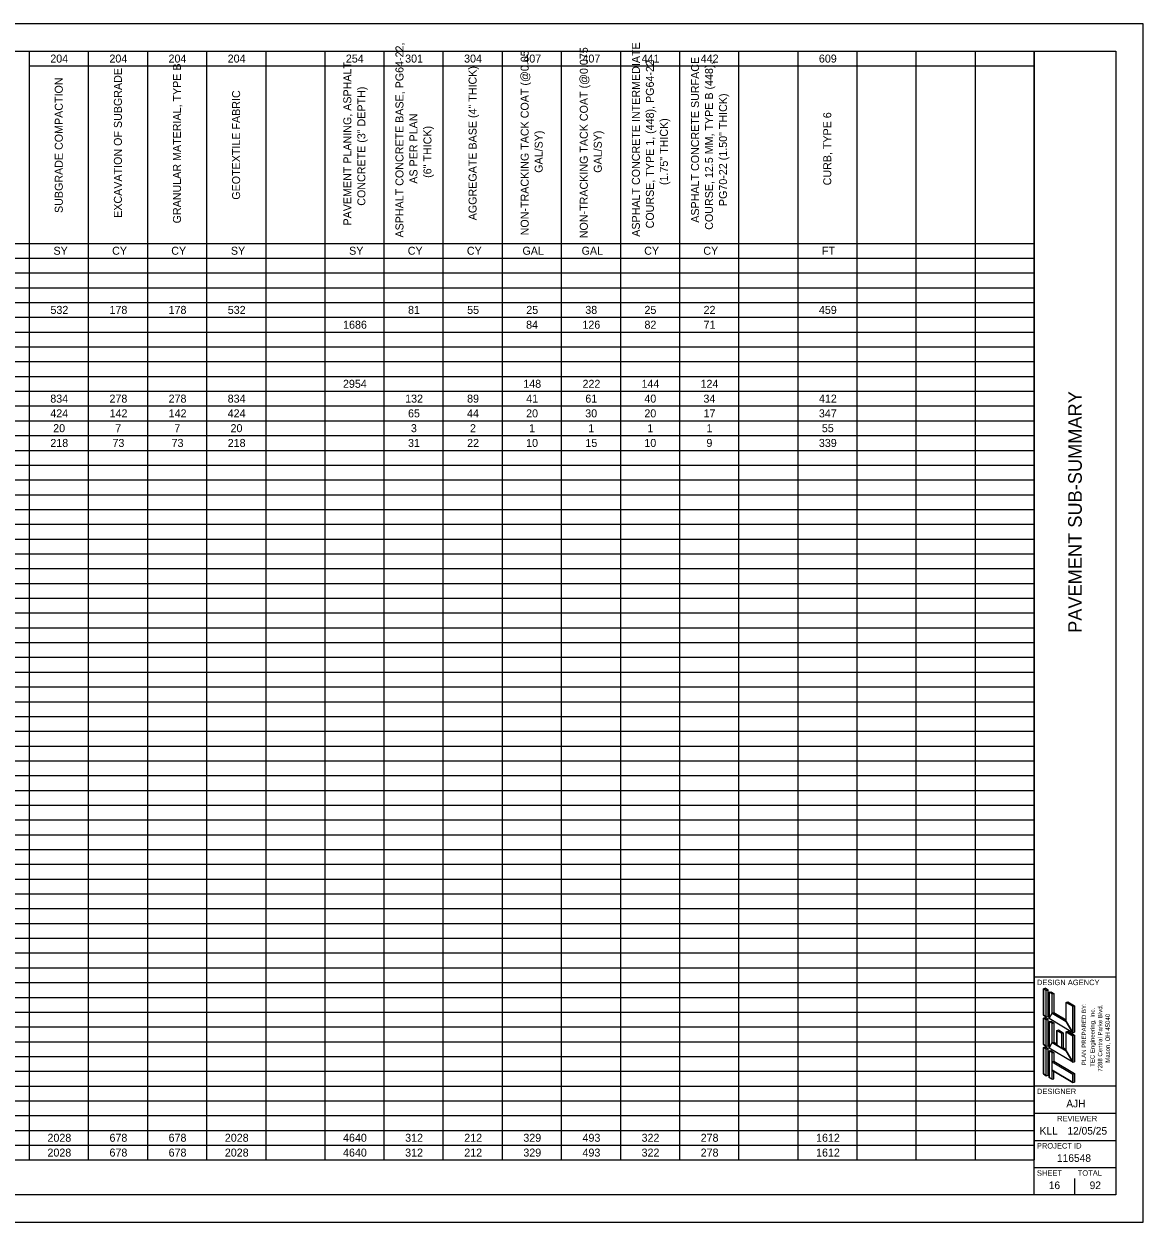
# Model space of a CAD drawing. Extents: x 0 to 34, y 0 to 22.
# Drawn here: x 13.44 to 34, y 0 to 22 of the extents above; entities that cross this region are included whole.
import ezdxf

# ---------------------------------------------------------------- set-up
doc = ezdxf.new("R2010")
doc.units = 0
for name, color, linetype in [('Default', 7, 'Continuous'), ('SH_Border', 7, 'Continuous'), ('SH_Cut_Line', 7, 'Continuous'), ('SH_Data', 7, 'Continuous'), ('SH_Text', 7, 'Continuous')]:
    doc.layers.add(name, color=color, linetype=linetype)

msp = doc.modelspace()

# ---------------------------------------------------------------- linework, layer by layer
at = {"layer": 'SH_Border'}
for p, q in [((32, 0.5), (32, 21.5)), ((32, 4.5), (33.5, 4.5)), ((32, 2.5), (33.5, 2.5)), ((32, 2), (33.5, 2)), ((32, 1.5), (33.5, 1.5)), ((32, 1), (33.5, 1))]:
    msp.add_line(p, q, dxfattribs=at)
msp.add_lwpolyline([(1.5, 21.5), (33.5, 21.5), (33.5, 0.5), (1.5, 0.5)], close=True, dxfattribs=at)
at = {"layer": 'SH_Cut_Line'}
msp.add_lwpolyline([(0, 0), (34, 0), (34, 22), (0, 22)], close=True, dxfattribs=at)
at = {"layer": 'SH_Data'}
for p, q in [((32.75, 3.5), (32.75, 3.5)), ((32.375, 0.675), (32.375, 0.675)), ((32.75, 0.5), (32.75, 0.8))]:
    msp.add_line(p, q, dxfattribs=at)
at = {"layer": 'SH_Text'}
for p, q in [((1.5, 21.5), (32, 21.5)), ((13.54, 21.5), (13.54, 1.14)), ((14.626, 21.5), (14.626, 1.14)), ((15.712, 21.5), (15.712, 1.14)), ((16.798, 21.5), (16.798, 1.14)), ((17.884, 21.5), (17.884, 1.14)), ((18.97, 21.5), (18.97, 1.14)), ((20.055, 21.5), (20.055, 1.14)), ((21.141, 21.5), (21.141, 1.14)), ((22.227, 21.5), (22.227, 1.14)), ((23.313, 21.5), (23.313, 1.14)), ((24.399, 21.5), (24.399, 1.14)), ((25.485, 21.5), (25.485, 1.14)), ((26.571, 21.5), (26.571, 1.14)), ((27.657, 21.5), (27.657, 1.14)), ((28.742, 21.5), (28.742, 1.14)), ((29.828, 21.5), (29.828, 1.14)), ((30.914, 21.5), (30.914, 1.14)), ((32, 21.5), (32, 1.14)), ((13.54, 21.229), (32, 21.229)), ((8.111, 17.971), (32, 17.971)), ((1.5, 17.699), (32, 17.699)), ((1.5, 17.428), (32, 17.428)), ((1.5, 17.157), (32, 17.157)), ((1.5, 16.885), (32, 16.885)), ((1.5, 16.614), (32, 16.614)), ((1.5, 16.342), (32, 16.342)), ((1.5, 16.071), (32, 16.071)), ((1.5, 15.799), (32, 15.799)), ((1.5, 15.528), (32, 15.528)), ((1.5, 15.256), (32, 15.256)), ((1.5, 14.985), (32, 14.985)), ((1.5, 14.713), (32, 14.713)), ((1.5, 14.442), (32, 14.442)), ((1.5, 14.17), (32, 14.17)), ((1.5, 13.899), (32, 13.899)), ((1.5, 13.627), (32, 13.627)), ((1.5, 13.356), (32, 13.356)), ((1.5, 13.085), (32, 13.085)), ((1.5, 12.813), (32, 12.813)), ((1.5, 12.542), (32, 12.542)), ((1.5, 12.27), (32, 12.27)), ((1.5, 11.999), (32, 11.999)), ((1.5, 11.727), (32, 11.727)), ((1.5, 11.456), (32, 11.456)), ((1.5, 11.184), (32, 11.184)), ((1.5, 10.913), (32, 10.913)), ((1.5, 10.641), (32, 10.641)), ((1.5, 10.37), (32, 10.37)), ((1.5, 10.098), (32, 10.098)), ((1.5, 9.827), (32, 9.827)), ((1.5, 9.555), (32, 9.555)), ((1.5, 9.284), (32, 9.284)), ((1.5, 9.013), (32, 9.013)), ((1.5, 8.741), (32, 8.741)), ((1.5, 8.47), (32, 8.47)), ((1.5, 8.198), (32, 8.198)), ((1.5, 7.927), (32, 7.927)), ((1.5, 7.655), (32, 7.655)), ((1.5, 7.384), (32, 7.384)), ((1.5, 7.112), (32, 7.112)), ((1.5, 6.841), (32, 6.841)), ((1.5, 6.569), (32, 6.569)), ((1.5, 6.298), (32, 6.298)), ((1.5, 6.026), (32, 6.026)), ((1.5, 5.755), (32, 5.755)), ((1.5, 5.484), (32, 5.484)), ((1.5, 5.212), (32, 5.212)), ((1.5, 4.941), (32, 4.941)), ((1.5, 4.669), (32, 4.669)), ((1.5, 4.398), (32, 4.398)), ((32.169, 4.285), (32.201, 4.294)), ((32.169, 3.799), (32.169, 4.285)), ((32.223, 4.253), (32.169, 4.285)), ((32.255, 4.261), (32.201, 4.294)), ((32.223, 4.253), (32.255, 4.261)), ((32.223, 3.767), (32.223, 4.253)), ((32.255, 3.775), (32.255, 4.261)), ((32.277, 4.221), (32.309, 4.229)), ((32.331, 4.188), (32.277, 4.221)), ((32.277, 3.735), (32.277, 4.221)), ((32.309, 4.229), (32.363, 4.196)), ((32.331, 4.188), (32.363, 4.196)), ((32.331, 3.837), (32.331, 4.188)), ((32.363, 4.196), (32.363, 3.845)), ((1.5, 4.126), (32, 4.126)), ((32.587, 4.034), (32.62, 4.042)), ((32.587, 3.683), (32.587, 4.034)), ((32.709, 3.961), (32.587, 4.034)), ((32.62, 4.042), (32.741, 3.97)), ((32.709, 3.961), (32.741, 3.97)), ((32.709, 3.475), (32.709, 3.961)), ((32.741, 3.97), (32.741, 3.484)), ((1.5, 3.855), (32, 3.855)), ((32.223, 3.767), (32.169, 3.799)), ((32.169, 3.745), (32.201, 3.754)), ((32.169, 3.259), (32.169, 3.745)), ((32.223, 3.713), (32.169, 3.745)), ((32.255, 3.722), (32.201, 3.754)), ((32.223, 3.767), (32.255, 3.775)), ((32.331, 3.837), (32.363, 3.845)), ((32.587, 3.683), (32.331, 3.837)), ((32.363, 3.845), (32.587, 3.711)), ((1.5, 3.583), (32, 3.583)), ((32.223, 3.713), (32.255, 3.722)), ((32.223, 3.227), (32.223, 3.713)), ((32.255, 3.236), (32.255, 3.722)), ((32.709, 3.475), (32.277, 3.735)), ((32.277, 3.681), (32.309, 3.689)), ((32.277, 3.195), (32.277, 3.681)), ((32.331, 3.648), (32.277, 3.681)), ((32.309, 3.689), (32.363, 3.656)), ((32.331, 3.648), (32.363, 3.656)), ((32.331, 3.297), (32.331, 3.648)), ((32.363, 3.656), (32.363, 3.305)), ((32.415, 3.519), (32.448, 3.527)), ((32.448, 3.527), (32.535, 3.474)), ((1.5, 3.312), (32, 3.312)), ((32.331, 3.297), (32.363, 3.305)), ((32.363, 3.305), (32.415, 3.274)), ((32.415, 3.519), (32.415, 3.247)), ((32.415, 3.519), (32.503, 3.466)), ((32.503, 3.466), (32.535, 3.474)), ((32.503, 3.466), (32.503, 3.194)), ((32.535, 3.474), (32.535, 3.202)), ((32.587, 3.494), (32.62, 3.502)), ((32.587, 3.143), (32.587, 3.494)), ((32.709, 3.421), (32.587, 3.494)), ((32.62, 3.502), (32.741, 3.43)), ((32.709, 3.475), (32.741, 3.484)), ((32.709, 3.421), (32.741, 3.43)), ((32.709, 2.935), (32.709, 3.421)), ((32.741, 3.43), (32.741, 2.944)), ((32.223, 3.227), (32.169, 3.259)), ((32.169, 3.205), (32.201, 3.215)), ((32.169, 2.719), (32.169, 3.205)), ((32.223, 3.173), (32.169, 3.205)), ((32.255, 3.181), (32.201, 3.215)), ((32.222, 3.173), (32.255, 3.181)), ((32.223, 3.227), (32.255, 3.236)), ((32.223, 2.687), (32.223, 3.173)), ((32.255, 2.695), (32.255, 3.181)), ((32.709, 2.935), (32.277, 3.195)), ((32.277, 3.141), (32.309, 3.151)), ((32.331, 3.108), (32.277, 3.141)), ((32.277, 2.655), (32.277, 3.141)), ((32.309, 3.151), (32.363, 3.116)), ((32.415, 3.247), (32.331, 3.297)), ((32.331, 3.108), (32.363, 3.116)), ((32.331, 2.944), (32.331, 3.108)), ((32.363, 3.116), (32.363, 2.952)), ((32.503, 3.194), (32.535, 3.202)), ((32.587, 3.143), (32.503, 3.194)), ((32.535, 3.202), (32.587, 3.171)), ((1.5, 3.04), (32, 3.04)), ((32.331, 2.944), (32.363, 2.952)), ((32.331, 2.944), (32.709, 2.717)), ((32.363, 2.952), (32.741, 2.725)), ((32.709, 2.935), (32.741, 2.944)), ((1.5, 2.769), (32, 2.769)), ((32.223, 2.687), (32.169, 2.719)), ((32.223, 2.687), (32.255, 2.695)), ((32.331, 2.622), (32.277, 2.655)), ((32.331, 2.787), (32.709, 2.56)), ((32.331, 2.622), (32.331, 2.787)), ((32.363, 2.63), (32.363, 2.767)), ((32.709, 2.717), (32.741, 2.725)), ((32.709, 2.56), (32.709, 2.717)), ((32.741, 2.725), (32.741, 2.568)), ((1.5, 2.497), (32, 2.497)), ((32.331, 2.622), (32.363, 2.63)), ((32.709, 2.56), (32.741, 2.568)), ((1.5, 2.226), (32, 2.226)), ((1.5, 1.954), (32, 1.954)), ((1.5, 1.683), (32, 1.683)), ((1.5, 1.412), (32, 1.412)), ((1.5, 1.14), (32, 1.14))]:
    msp.add_line(p, q, dxfattribs=at)
for points in [[(32.169, 3.799), (32.223, 3.767), (32.223, 4.253), (32.169, 4.285)], [(32.277, 3.735), (32.331, 3.837), (32.331, 4.188), (32.277, 4.221)], [(32.709, 3.475), (32.587, 3.683), (32.587, 4.034), (32.709, 3.961)], [(32.169, 3.259), (32.223, 3.227), (32.223, 3.713), (32.169, 3.745)], [(32.277, 3.735), (32.331, 3.837), (32.587, 3.683), (32.709, 3.475)], [(32.277, 3.195), (32.331, 3.297), (32.331, 3.648), (32.277, 3.681)], [(32.415, 3.247), (32.415, 3.519), (32.503, 3.466), (32.503, 3.194)], [(32.709, 2.935), (32.587, 3.143), (32.587, 3.494), (32.709, 3.421)], [(32.169, 2.719), (32.223, 2.687), (32.223, 3.173), (32.169, 3.205)], [(32.277, 3.195), (32.331, 3.297), (32.587, 3.143), (32.709, 2.935)], [(32.277, 2.655), (32.331, 2.622), (32.331, 3.108), (32.277, 3.141)], [(32.331, 2.787), (32.331, 2.944), (32.709, 2.717), (32.709, 2.56)]]:
    msp.add_lwpolyline(points, close=True, dxfattribs=at)

# ---------------------------------------------------------------- texts
at = {"layer": 'Default'}
for s, p in [('PLAN PREPARED BY:', (32.954, 2.88)), ('TEC Engineering, Inc.', (33.11, 2.851)), ('7288 Central Parke Blvd.', (33.25, 2.762)), ('Mason, OH 45040', (33.39, 2.925))]:
    msp.add_text(s, height=0.08, rotation=90, dxfattribs=at).set_placement(p)
at = {"layer": 'SH_Data'}
msp.add_text('PAVEMENT SUB-SUMMARY', height=0.25, rotation=90, dxfattribs=at).set_placement((32.875, 10.818))
for s, height, p in [('DESIGN AGENCY', 0.1, (32.05, 4.35)), ('DESIGNER', 0.1, (32.05, 2.35)), ('AJH', 0.14, (32.59, 2.105)), ('REVIEWER', 0.1, (32.422, 1.85)), ('KLL', 0.14, (32.101, 1.605)), ('12/05/25', 0.14, (32.611, 1.605)), ('PROJECT ID', 0.1, (32.05, 1.35)), ('116548', 0.14, (32.419, 1.105)), ('SHEET', 0.1, (32.05, 0.85)), ('TOTAL', 0.1, (32.8, 0.85)), ('16', 0.14, (32.268, 0.605)), ('92', 0.14, (33.019, 0.605))]:
    msp.add_text(s, height=height, dxfattribs=at).set_placement(p)
at = {"layer": 'SH_Text'}
for s, height, p in [('ASPHALT CONCRETE BASE, PG64-22, ', 0.14691, (20.415, 18.078)), ('NON-TRACKING TACK COAT (@0.075 ', 0.14691, (23.801, 18.065)), ('ASPHALT CONCRETE INTERMEDIATE ', 0.14691, (24.758, 18.093)), ('NON-TRACKING TACK COAT (@0.05 ', 0.14691, (22.715, 18.118)), ('ASPHALT CONCRETE SURFACE ', 0.14691, (25.844, 18.35)), ('EXCAVATION OF SUBGRADE', 0.14691, (15.243, 18.44)), ('GRANULAR MATERIAL, TYPE B', 0.14691, (16.328, 18.338)), ('PAVEMENT PLANING, ASPHALT ', 0.14691, (19.457, 18.299)), ('AGGREGATE BASE (4" THICK)', 0.14691, (21.758, 18.395)), ('COURSE, TYPE 1, (448), PG64-22 ', 0.14691, (25.015, 18.246)), ('COURSE, 12.5 MM, TYPE B (448), ', 0.14691, (26.101, 18.22)), ('SUBGRADE COMPACTION', 0.14691, (14.157, 18.529)), ('GEOTEXTILE FABRIC', 0.14691, (17.414, 18.773)), ('CONCRETE (3" DEPTH)', 0.14691, (19.715, 18.662)), ('PG70-22 (1.50" THICK)', 0.14691, (26.358, 18.656)), ('AS PER PLAN', 0.14691, (20.672, 19.067)), ('(1.75" THICK)', 0.14691, (25.272, 19.042)), ('CURB, TYPE 6', 0.14691, (28.273, 19.036)), ('(6" THICK)', 0.1469, (20.929, 19.174)), ('GAL/SY)', 0.1469, (22.972, 19.267)), ('GAL/SY)', 0.1469, (24.058, 19.267))]:
    msp.add_text(s, height=height, rotation=90, dxfattribs=at).set_placement(p)
for s, height, p in [('204', 0.1469, (13.928, 21.291)), ('204', 0.1469, (15.014, 21.291)), ('204', 0.1469, (16.1, 21.291)), ('204', 0.1469, (17.186, 21.291)), ('254', 0.1469, (19.357, 21.291)), ('301', 0.1469, (20.446, 21.291)), ('304', 0.1469, (21.529, 21.291)), ('407', 0.1469, (22.617, 21.291)), ('407', 0.1469, (23.703, 21.291)), ('441', 0.1469, (24.789, 21.291)), ('442', 0.1469, (25.875, 21.291)), ('609', 0.1469, (28.046, 21.291)), ('SY', 0.1469, (13.987, 17.762)), ('CY', 0.1469, (15.064, 17.762)), ('CY', 0.1469, (16.15, 17.762)), ('SY', 0.1469, (17.245, 17.762)), ('SY', 0.1469, (19.417, 17.762)), ('CY', 0.1469, (20.494, 17.762)), ('CY', 0.1469, (21.58, 17.762)), ('GAL', 0.1469, (22.601, 17.762)), ('GAL', 0.1469, (23.687, 17.762)), ('CY', 0.1469, (24.837, 17.762)), ('CY', 0.1469, (25.923, 17.762)), ('FT', 0.1469, (28.102, 17.762)), ('532', 0.1469, (13.931, 16.676)), ('178', 0.1469, (15.015, 16.676)), ('178', 0.1469, (16.101, 16.676)), ('532', 0.1469, (17.188, 16.676)), ('81', 0.1469, (20.499, 16.676)), ('55', 0.1469, (21.585, 16.676)), ('25', 0.1469, (22.671, 16.676)), ('38', 0.1469, (23.755, 16.676)), ('25', 0.1469, (24.842, 16.676)), ('22', 0.1469, (25.928, 16.676)), ('459', 0.1469, (28.046, 16.676)), ('1686', 0.1469, (19.306, 16.404)), ('84', 0.1469, (22.668, 16.404)), ('126', 0.1469, (23.702, 16.404)), ('82', 0.1469, (24.842, 16.404)), ('71', 0.1469, (25.928, 16.404)), ('2954', 0.1469, (19.304, 15.319)), ('148', 0.1469, (22.616, 15.319)), ('222', 0.1469, (23.704, 15.319)), ('144', 0.1469, (24.787, 15.319)), ('124', 0.1469, (25.872, 15.319)), ('834', 0.1469, (13.928, 15.047)), ('278', 0.1469, (15.015, 15.047)), ('278', 0.1469, (16.101, 15.047)), ('834', 0.1469, (17.186, 15.047)), ('132', 0.1469, (20.446, 15.047)), ('89', 0.1469, (21.584, 15.047)), ('41', 0.1469, (22.67, 15.047)), ('61', 0.1469, (23.756, 15.047)), ('40', 0.1469, (24.84, 15.047)), ('34', 0.1469, (25.925, 15.047)), ('412', 0.1469, (28.047, 15.047)), ('424', 0.1469, (13.928, 14.776)), ('142', 0.1469, (15.017, 14.776)), ('142', 0.1469, (16.102, 14.776)), ('424', 0.1469, (17.186, 14.776)), ('65', 0.1469, (20.499, 14.776)), ('44', 0.1469, (21.582, 14.776)), ('20', 0.1469, (22.668, 14.776)), ('30', 0.1469, (23.754, 14.776)), ('20', 0.1469, (24.84, 14.776)), ('17', 0.1469, (25.927, 14.776)), ('347', 0.1469, (28.046, 14.776)), ('20', 0.1469, (13.981, 14.504)), ('7', 0.147, (15.121, 14.504)), ('7', 0.147, (16.207, 14.504)), ('20', 0.1469, (17.239, 14.504)), ('3', 0.147, (20.552, 14.504)), ('2', 0.147, (21.637, 14.504)), ('1', 0.147, (22.723, 14.504)), ('1', 0.147, (23.809, 14.504)), ('1', 0.147, (24.895, 14.504)), ('1', 0.147, (25.981, 14.504)), ('55', 0.1469, (28.1, 14.504)), ('218', 0.1469, (13.929, 14.233)), ('73', 0.1469, (15.07, 14.233)), ('73', 0.1469, (16.156, 14.233)), ('218', 0.1469, (17.187, 14.233)), ('31', 0.1469, (20.499, 14.233)), ('22', 0.1469, (21.585, 14.233)), ('10', 0.1469, (22.668, 14.233)), ('15', 0.1469, (23.757, 14.233)), ('10', 0.1469, (24.84, 14.233)), ('9', 0.147, (25.98, 14.233)), ('339', 0.1469, (28.046, 14.233)), ('2028', 0.1469, (13.876, 1.474)), ('678', 0.1469, (15.015, 1.474)), ('678', 0.1469, (16.101, 1.474)), ('2028', 0.1469, (17.134, 1.474)), ('4640', 0.1469, (19.305, 1.474)), ('312', 0.1469, (20.446, 1.474)), ('212', 0.1469, (21.532, 1.474)), ('329', 0.1469, (22.617, 1.474)), ('493', 0.1469, (23.704, 1.474)), ('322', 0.1469, (24.789, 1.474)), ('278', 0.1469, (25.874, 1.474)), ('1612', 0.1469, (27.994, 1.474)), ('2028', 0.1469, (13.876, 1.202)), ('678', 0.1469, (15.015, 1.202)), ('678', 0.1469, (16.101, 1.202)), ('2028', 0.1469, (17.134, 1.202)), ('4640', 0.1469, (19.305, 1.202)), ('312', 0.1469, (20.446, 1.202)), ('212', 0.1469, (21.532, 1.202)), ('329', 0.1469, (22.617, 1.202)), ('493', 0.1469, (23.704, 1.202)), ('322', 0.1469, (24.789, 1.202)), ('278', 0.1469, (25.874, 1.202)), ('1612', 0.1469, (27.994, 1.202))]:
    msp.add_text(s, height=height, dxfattribs=at).set_placement(p)

doc.saveas('drawing.dxf')
